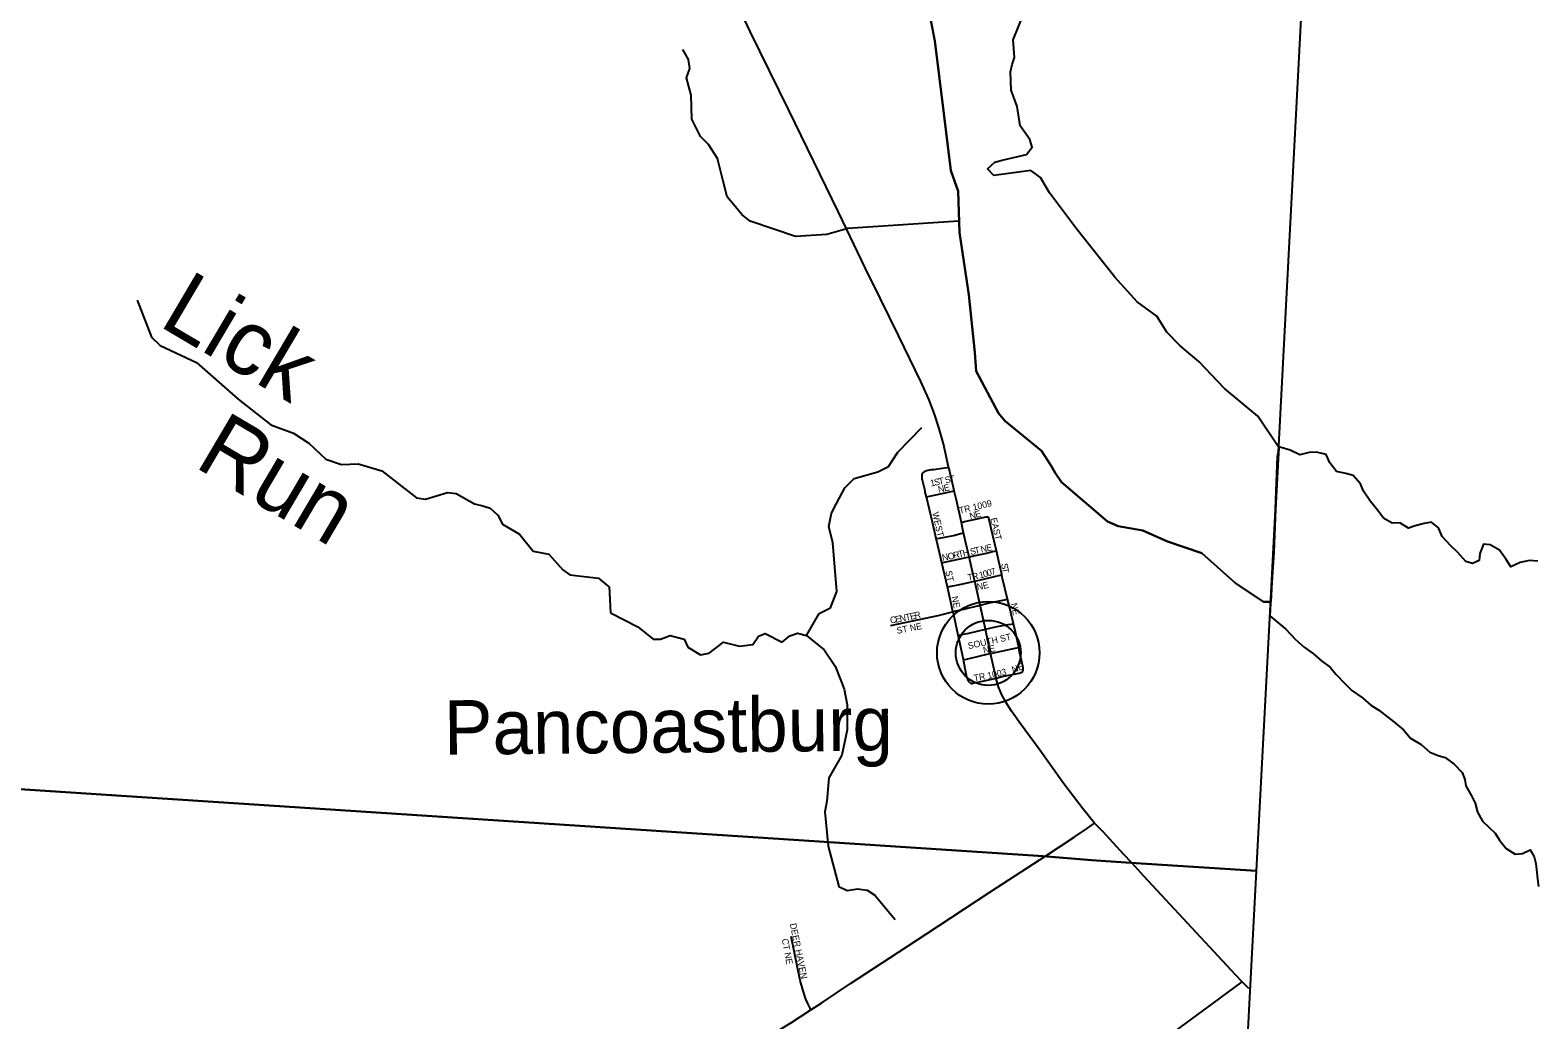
# Model space of a CAD drawing. Extents: x -51392 to 1635000, y 156707 to 696232.
# Drawn here: x 180473 to 192031, y 515913 to 523500 of the extents above; entities that cross this region are included whole.
import ezdxf

# ---------------------------------------------------------------- set-up
doc = ezdxf.new("R2010")
doc.units = 0
for name, color, linetype in [('GM_X_Adjacent_County', 7, 'Continuous'), ('GM_X_County', 7, 'Continuous'), ('GM_X_County_Road', 7, 'Continuous'), ('GM_X_Major_Lake', 7, 'Continuous'), ('GM_X_Minor_River', 7, 'Continuous'), ('GM_X_Minor_River_Text', 7, 'Continuous'), ('GM_X_State_Route', 7, 'Continuous'), ('GM_X_Township', 7, 'Continuous'), ('GM_X_Township_Road', 7, 'Continuous'), ('GM_X_Township_Subdivision', 7, 'Continuous'), ('GM_X_Township_Subdivision_Text', 7, 'Continuous'), ('GM_X_Unincorporated', 7, 'Continuous'), ('GM_X_Unincorporated_Text', 7, 'Continuous')]:
    doc.layers.add(name, color=color, linetype=linetype)

msp = doc.modelspace()

# ---------------------------------------------------------------- linework, layer by layer
at = {"layer": 'GM_X_Adjacent_County'}
msp.add_lwpolyline([(192517, 562951), (192280, 559515), (192063, 555533), (191849, 551619), (191828, 551227), (191474, 544744), (191470, 544658), (190603, 531017), (189983, 519189), (189871, 517055), (189823, 516133), (189395, 507976), (188717, 497545), (188564, 495053), (188562, 495018), (188420, 492711), (187477, 479338), (192583, 479108), (200837, 478683), (211027, 478155)], dxfattribs=at)
at = {"layer": 'GM_X_County'}
msp.add_lwpolyline([(167692, 546175), (177006, 545575), (182001, 545258), (186228, 544990), (191470, 544658), (190603, 531017), (189983, 519189), (189871, 517055), (189823, 516133), (189395, 507976), (188717, 497545), (188564, 495053), (188562, 495018), (188420, 492711), (187477, 479338), (185070, 475300), (185032, 475236), (184665, 474619), (182037, 470210), (180454, 467533), (177674, 462830)], dxfattribs=at)
at = {"layer": 'GM_X_County_Road'}
for points in [[(188252, 517166), (188476, 517313), (188579, 517383), (188633, 517420)], [(186458, 515989), (186543, 516044), (186761, 516190), (187063, 516387), (187337, 516567), (187831, 516891), (188215, 517142), (188252, 517166)], [(179810, 512968), (180044, 513071), (180794, 513403), (181288, 513624), (181678, 513796), (181813, 513856), (182187, 514024), (183011, 514390), (183251, 514496), (183505, 514610), (183955, 514810), (184225, 514930), (184450, 515030), (184750, 515163), (185050, 515295), (185259, 515389), (185724, 515595), (185948, 515697), (186066, 515754), (186139, 515792), (186225, 515841), (186309, 515892), (186458, 515989)]]:
    msp.add_lwpolyline(points, dxfattribs=at)
at = {"layer": 'GM_X_Major_Lake'}
msp.add_line((190045, 520305), (189975, 519011), dxfattribs=at)
for points in [[(190045, 520300), (190044, 520282), (190036, 520232), (190006, 519496), (189991, 519269), (189983, 519117), (189927, 519117), (189713, 519260), (189456, 519490), (189193, 519579), (189003, 519663), (188814, 519697), (188732, 519733), (188379, 520035), (188331, 520105), (188299, 520159), (188227, 520275), (187944, 520504), (187896, 520564), (187726, 520885), (187716, 521030), (187670, 521471), (187598, 521949), (187588, 522266), (187532, 522424), (187478, 522861), (187408, 523419), (187362, 523654)], [(187362, 523654), (187408, 523419), (187478, 522861), (187532, 522424), (187588, 522266), (187598, 521949), (187670, 521471), (187716, 521030), (187726, 520885), (187896, 520564), (187944, 520504), (188227, 520275), (188299, 520159), (188331, 520105), (188379, 520035), (188732, 519733), (188814, 519697), (189003, 519663), (189193, 519579), (189456, 519490), (189713, 519260), (189927, 519117), (189983, 519117), (189991, 519269), (190006, 519496), (190036, 520232), (190044, 520282), (190045, 520300)], [(190045, 520300), (189884, 520541), (189629, 520754), (189433, 520961), (189290, 521079), (189186, 521184), (189110, 521308), (188960, 521418), (188787, 521607), (188493, 521976), (188286, 522253), (188218, 522370), (188144, 522424), (187861, 522386), (187813, 522436), (187867, 522488), (187925, 522504), (188110, 522548), (188154, 522602), (188136, 522662), (188062, 522767), (188040, 522915), (187994, 523040), (187988, 523180), (188002, 523238), (188018, 523290), (188008, 523427), (188096, 523641)], [(192031, 519428), (191967, 519434), (191895, 519418), (191824, 519386), (191787, 519443), (191737, 519513), (191665, 519553), (191614, 519559), (191586, 519487), (191580, 519435), (191530, 519411), (191478, 519427), (191414, 519498), (191362, 519548), (191298, 519618), (191270, 519685), (191216, 519729), (191158, 519717), (191090, 519699), (191039, 519683), (190973, 519724), (190913, 519720), (190847, 519758), (190805, 519818), (190747, 519887), (190695, 519965), (190671, 520023), (190616, 520087), (190559, 520100), (190487, 520116), (190437, 520182), (190407, 520246), (190333, 520265), (190277, 520263), (190205, 520243), (190131, 520281), (190045, 520305)], [(189975, 519011), (190098, 518909), (190174, 518829), (190240, 518771), (190312, 518719), (190374, 518663), (190438, 518617), (190482, 518564), (190550, 518492), (190606, 518438), (190686, 518382), (190750, 518324), (190812, 518286), (190926, 518197), (191002, 518137), (191054, 518073), (191136, 518023), (191202, 517965), (191266, 517939), (191319, 517923), (191389, 517874), (191451, 517808), (191471, 517756), (191479, 517706), (191521, 517630), (191551, 517574), (191567, 517505), (191607, 517437), (191703, 517343), (191737, 517289), (191789, 517227), (191857, 517182), (191913, 517188), (191973, 517217), (192003, 517162), (192015, 517112), (192023, 517042), (192027, 516990), (192035, 516934)]]:
    msp.add_lwpolyline(points, dxfattribs=at)
at = {"layer": 'GM_X_Minor_River'}
for points in [[(187590, 522036), (186742, 521979), (186581, 521933), (186341, 521917), (185992, 522036), (185928, 522086), (185817, 522222), (185785, 522343), (185741, 522517), (185673, 522624), (185611, 522686), (185545, 522818), (185539, 523001), (185505, 523135), (185531, 523207), (185519, 523274), (185477, 523352)], [(181293, 521430), (181403, 521147), (181469, 521083), (181748, 520953), (182068, 520672), (182319, 520473), (182491, 520411), (182610, 520334), (182740, 520212), (182860, 520170), (182987, 520174), (183169, 520121), (183436, 519915), (183504, 519905), (183672, 519955), (183739, 519949), (183879, 519868), (183943, 519854), (183999, 519836), (184059, 519782), (184094, 519712), (184224, 519636), (184328, 519505), (184450, 519483), (184557, 519363), (184611, 519324), (184829, 519298), (184906, 519234), (184911, 519234)], [(186522, 519027), (186608, 519071), (186658, 519197), (186626, 519570), (186596, 519694), (186616, 519797), (186651, 519867), (186717, 519991), (186791, 520063), (186972, 520115), (187052, 520156), (187124, 520264), (187309, 520454)], [(184911, 519234), (184922, 519034)], [(184922, 519034), (185132, 518926), (185250, 518832), (185304, 518832), (185380, 518860), (185486, 518830), (185514, 518770), (185612, 518711), (185678, 518723), (185788, 518807), (185910, 518777), (186014, 518789), (186056, 518855), (186108, 518875), (186238, 518809), (186296, 518857), (186356, 518877), (186424, 518859), (186560, 518750), (186644, 518624), (186692, 518502), (186714, 518448), (186736, 518327), (186736, 518137), (186696, 517941), (186596, 517767), (186580, 517588), (186566, 517508), (186590, 517244)], [(186424, 518859), (186522, 519027)], [(186590, 517244), (186671, 516935), (186737, 516903), (186815, 516917), (186889, 516907), (186947, 516869), (187105, 516682)]]:
    msp.add_lwpolyline(points, dxfattribs=at)
at = {"layer": 'GM_X_State_Route'}
for points in [[(186906, 521615), (186669, 522104), (186289, 522886), (185993, 523489), (185887, 523711)], [(187514, 520153), (187474, 520328), (187439, 520455), (187404, 520564), (187362, 520671), (187300, 520806), (187129, 521160), (186920, 521587), (186906, 521615)], [(188066, 518182), (187996, 518279), (187952, 518347), (187921, 518405), (187896, 518465), (187879, 518527), (187878, 518532), (187836, 518722), (187796, 518907), (187755, 519091), (187714, 519276), (187703, 519327), (187671, 519461), (187643, 519581), (187629, 519645), (187616, 519709), (187612, 519726), (187573, 519897), (187557, 519967), (187551, 519995), (187515, 520148), (187514, 520153)], [(188695, 517356), (188653, 517401), (188633, 517420), (188546, 517527), (188397, 517721), (188207, 517988), (188066, 518182)], [(189815, 516153), (189765, 516205), (189716, 516255), (189213, 516798), (189011, 517015), (188918, 517116), (188855, 517184), (188695, 517356)]]:
    msp.add_lwpolyline(points, dxfattribs=at)
at = {"layer": 'GM_X_Township'}
for points in [[(167692, 546175), (177006, 545575), (182001, 545258), (186228, 544990), (191470, 544658), (190603, 531017), (189983, 519189), (189871, 517055), (188911, 517117), (188608, 517138), (188239, 517168), (177580, 517864), (162392, 518660)], [(162392, 518660), (177580, 517864), (188239, 517168), (188608, 517138), (188911, 517117), (189871, 517055), (189823, 516133), (189395, 507976), (188717, 497545)]]:
    msp.add_lwpolyline(points, dxfattribs=at)
at = {"layer": 'GM_X_Township_Road'}
msp.add_lwpolyline([(189222, 515806), (189539, 516039), (189765, 516205)], dxfattribs=at)
at = {"layer": 'GM_X_Township_Subdivision'}
for points in [[(187343, 519922), (187335, 519959), (187333, 519969), (187314, 520050), (187312, 520058), (187311, 520065), (187310, 520074), (187310, 520080), (187310, 520088), (187312, 520098)], [(187312, 520098), (187317, 520106), (187318, 520108), (187320, 520110), (187324, 520113), (187327, 520115), (187330, 520117), (187333, 520119), (187343, 520123), (187356, 520127), (187370, 520129), (187383, 520131), (187399, 520133), (187501, 520146), (187515, 520148)], [(187343, 519922), (187366, 519927), (187380, 519931), (187524, 519961), (187557, 519967)], [(187418, 519602), (187389, 519729), (187343, 519922)], [(187612, 519726), (187635, 519732), (187696, 519747), (187801, 519769), (187806, 519770), (187810, 519769), (187814, 519768)], [(187881, 519509), (187841, 519680), (187822, 519758), (187821, 519761), (187819, 519764), (187817, 519766), (187814, 519768)], [(187418, 519602), (187443, 519606), (187552, 519627), (187598, 519638), (187629, 519645)], [(187461, 519417), (187443, 519496), (187418, 519602)], [(187461, 519417), (187483, 519421), (187626, 519451), (187671, 519461)], [(187504, 519231), (187461, 519417)], [(187671, 519461), (187804, 519491), (187851, 519502), (187881, 519509)], [(187921, 519326), (187897, 519438), (187881, 519509)], [(187714, 519276), (187738, 519282), (187866, 519311), (187909, 519322), (187921, 519326)], [(187965, 519138), (187927, 519296), (187921, 519326)], [(187504, 519231), (187520, 519235), (187588, 519248), (187714, 519276)], [(187547, 519042), (187504, 519231)], [(187547, 519042), (187621, 519059), (187755, 519091)], [(187755, 519091), (187815, 519106), (187929, 519131), (187965, 519138)], [(188011, 518949), (188005, 518971), (187975, 519099), (187965, 519138)], [(187068, 518936), (187071, 518936), (187080, 518938), (187178, 518958), (187433, 519012), (187543, 519041), (187547, 519042)], [(187587, 518861), (187550, 519031), (187547, 519042)], [(187796, 518907), (187887, 518927), (187971, 518943), (187991, 518946), (188011, 518949)], [(188051, 518768), (188028, 518875), (188011, 518949)], [(187587, 518861), (187614, 518867), (187668, 518878), (187796, 518907)], [(187627, 518674), (187602, 518793), (187587, 518861)], [(187627, 518674), (187651, 518679), (187829, 518720), (187836, 518722)], [(187836, 518722), (188023, 518762), (188051, 518768)], [(188084, 518589), (188085, 518594), (188086, 518599), (188086, 518606), (188085, 518613), (188083, 518625), (188058, 518733), (188051, 518768)], [(187661, 518520), (187660, 518524), (187654, 518540), (187641, 518604), (187627, 518674)], [(187675, 518498), (187670, 518503), (187668, 518507), (187662, 518517), (187661, 518520)], [(187675, 518498), (187681, 518494), (187684, 518493), (187687, 518492), (187692, 518492), (187697, 518492), (187700, 518493), (187799, 518513), (187878, 518532)], [(187878, 518532), (187924, 518544), (188055, 518571), (188062, 518573), (188068, 518575), (188075, 518578), (188080, 518581), (188083, 518585), (188084, 518589)], [(186458, 515989), (186452, 516001), (186435, 516038), (186419, 516071), (186398, 516134), (186376, 516213), (186306, 516551)]]:
    msp.add_lwpolyline(points, dxfattribs=at)
at = {"layer": 'GM_X_Unincorporated'}
for radius in [393, 249]:
    msp.add_circle((187818, 518726), radius, dxfattribs=at)

# ---------------------------------------------------------------- texts
at = {"layer": 'GM_X_Minor_River_Text'}
for s, p in [('Lick', (181449, 521239)), ('Run', (181722, 520158))]:
    msp.add_text(s, height=500, rotation=329.45, dxfattribs=at).set_placement(p)
at = {"layer": 'GM_X_Township_Subdivision_Text'}
for s, rotation, p in [('1', 11.7873, (187378, 520001)), ('S', 11.7796, (187408, 520007)), ('T', 11.7935, (187442, 520015)), ('N', 13.0958, (187439, 519953)), ('E', 14.0713, (187483, 519963)), ('S', 11.7574, (187490, 520024)), ('T', 8.6532, (187524, 520032)), ('TR 1009', 13.4483, (187600, 519792)), ('WEST', 282.4258, (187388, 519800)), ('N', 14.6225, (187681, 519749)), ('E', 15.8371, (187724, 519761)), ('EAST', 283.4127, (187833, 519756)), ('H', 12.2685, (187628, 519464)), ('S', 12.2611, (187684, 519476)), ('T', 12.2856, (187718, 519484)), ('N', 12.2685, (187765, 519494)), ('E', 12.5619, (187809, 519504)), ('N', 12.2685, (187469, 519430)), ('O', 12.2685, (187512, 519439)), ('R', 12.2841, (187555, 519448)), ('T', 12.2856, (187593, 519457)), ('S', 279.9515, (187916, 519408)), ('ST', 281.1665, (187489, 519352)), ('T', 10.643, (187664, 519278)), ('R', 11.3538, (187699, 519284)), ('1', 14.7464, (187754, 519296)), ('0', 15.0117, (187784, 519304)), ('0', 15.0262, (187814, 519312)), ('7', 14.9913, (187843, 519320)), ('T', 279.9515, (187922, 519374)), ('N', 9.2714, (187734, 519207)), ('E', 13.6085, (187782, 519215)), ('NE', 282.4226, (187535, 519155)), ('NE', 282.4203, (187989, 519102)), ('C', 9.6614, (187069, 518951)), ('E', 9.6731, (187108, 518957)), ('ST NE', 11.2515, (187120, 518871)), ('N', 10.4272, (187143, 518964)), ('T', 12.3105, (187188, 518972)), ('E', 12.6396, (187223, 518979)), ('R', 12.6248, (187257, 518987)), ('SOUTH ST', 12.5158, (187667, 518754)), ('NE', 12.4306, (187784, 518720)), ('1003', 12.6269, (187816, 518526)), ('NE', 19.9819, (188008, 518572)), ('TR', 9.9969, (187711, 518508)), ('DEER HAVEN', 281.5961, (186296, 516648)), ('CT NE', 280.7146, (186234, 516531))]:
    msp.add_text(s, height=50, rotation=rotation, dxfattribs=at).set_placement(p)
at = {"layer": 'GM_X_Unincorporated_Text'}
msp.add_text('Pancoastburg', height=417, rotation=0.5386, dxfattribs=at).set_placement((183647, 517945))

doc.saveas('drawing.dxf')
